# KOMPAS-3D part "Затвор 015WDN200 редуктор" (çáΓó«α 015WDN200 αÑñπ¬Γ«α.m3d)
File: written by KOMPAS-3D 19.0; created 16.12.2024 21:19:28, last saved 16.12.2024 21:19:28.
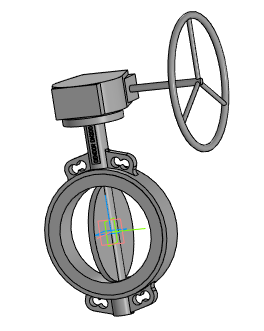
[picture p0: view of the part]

Document properties: Автор: Евгений; Полное имя файла: ..\Затвор 015WDN200 редуктор.a3d

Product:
- Part/product: Затвор 015WDN200 редуктор
    Масса: 31.4652

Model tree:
1. Операция без истории:1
